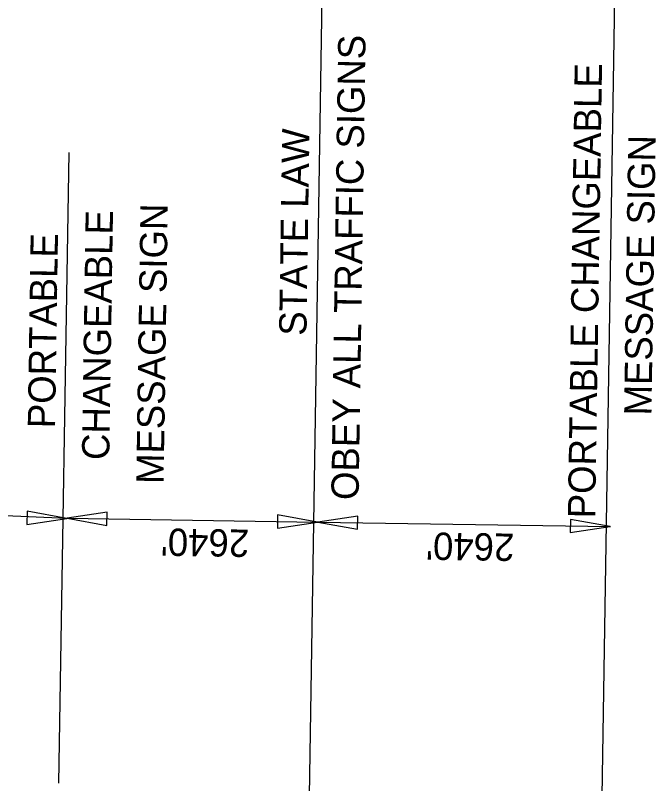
# Model space of a CAD drawing. Extents: x 2155255 to 2162649, y 140388 to 141878.
# Drawn here: x 2158823.7 to 2158964.2, y 140786.7 to 140955.4 of the extents above; entities that cross this region are included whole.
import ezdxf

# ---------------------------------------------------------------- set-up
doc = ezdxf.new("R2010")
doc.units = 0
for name, color, linetype in [('Default', 7, 'Continuous'), ('PR_Dimensions_Phase4', 7, 'Continuous'), ('T_PHASE_4', 7, 'Continuous')]:
    doc.layers.add(name, color=color, linetype=linetype)

# ---------------------------------------------------------------- blocks, each defined once
blk = doc.blocks.new('Arrowhd')
at = {"layer": 'Default'}
blk.add_lwpolyline([(0.3175, -0.0529), (0.3175, 0.0529), (0, 0)], close=True, dxfattribs=at)

msp = doc.modelspace()

# ---------------------------------------------------------------- linework, layer by layer
at = {"layer": 'PR_Dimensions_Phase4'}
for p, q in [((2158888.18, 140784.04), (2158891.29, 140977.61)), ((2158952.45, 140783.94), (2158955.34, 140969.65)), ((2158833.23, 140786.82), (2158835.43, 140925.3)), ((2158788.77, 140847.13), (2158835.03, 140844.98)), ((2158835.03, 140844.98), (2158890.03, 140844.15)), ((2158890.03, 140844.15), (2158954.27, 140843.18))]:
    msp.add_line(p, q, dxfattribs=at)

# ---------------------------------------------------------------- block references
for p, xscale, yscale, rotation in [((2158834.94, 140844.97), 27.559000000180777, 27.55900000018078, 179.13349016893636), ((2158835.03, 140844.98), 27.559000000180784, 27.559000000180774, -0.8665098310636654), ((2158889.93, 140844.14), 27.559000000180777, 27.55900000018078, 179.13349016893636), ((2158890.03, 140844.15), 27.559000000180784, 27.559000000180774, -0.8665098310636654), ((2158890.03, 140844.15), 27.559000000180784, 27.559000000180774, -0.8665098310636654), ((2158954.18, 140843.16), 27.559000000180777, 27.55900000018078, 179.13349016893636)]:
    msp.add_blockref('Arrowhd', p, dxfattribs=dict(at, xscale=xscale, yscale=yscale, rotation=rotation))

# ---------------------------------------------------------------- texts
at = {"layer": 'T_PHASE_4'}
for s, rotation, p in [('OBEY ALL TRAFFIC SIGNS', 89.1335, (2158898.97, 140848.96)), ('PORTABLE CHANGEABLE', 89.1335, (2158950.89, 140844.94)), ('STATE LAW', 89.1335, (2158887.52, 140885.02)), ('MESSAGE SIGN', 89.1335, (2158963.23, 140867.52)), ('MESSAGE SIGN', 89.1335, (2158856.18, 140852.48)), ('CHANGEABLE', 89.1335, (2158844.26, 140857.74)), ('PORTABLE ', 89.1335, (2158832.37, 140864.72)), ("2640'", 179.1335, (2158875.01, 140842.48)), ("2640'", 179.1335, (2158933.2, 140841.6))]:
    msp.add_text(s, height=6, rotation=rotation, dxfattribs=at).set_placement(p)

doc.saveas('drawing.dxf')
